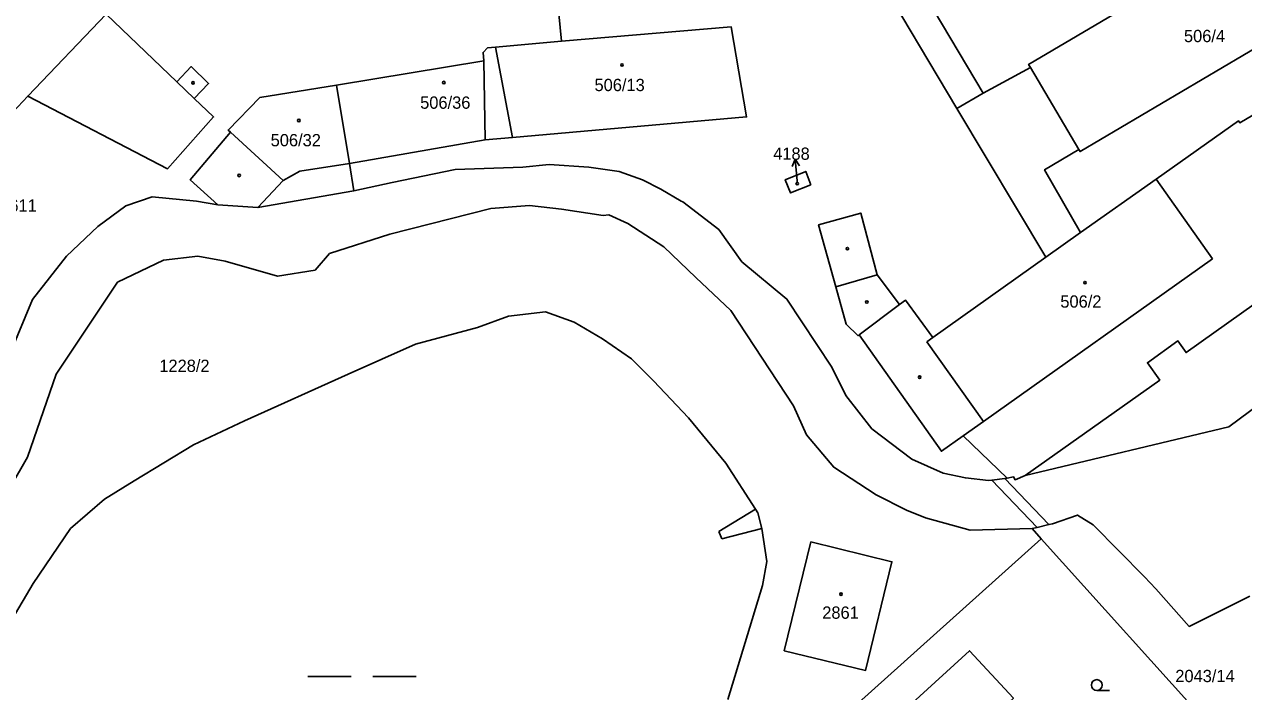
# Model space of a CAD drawing. Extents: x -679220 to -673243, y -1075091 to -1066557.
# Drawn here: x -677024.2 to -676855.4, y -1070809.1 to -1070716.7 of the extents above; entities that cross this region are included whole.
import ezdxf

# ---------------------------------------------------------------- set-up
doc = ezdxf.new("R2010")
doc.units = 0
for name, color, linetype in [('Hranice parcel', 7, 'Continuous'), ('Parcelní čísla', 7, 'Continuous'), ('Pop  PČ popisy', 7, 'Continuous'), ('Vnitřní kresba', 7, 'Continuous'), ('Značky budov', 7, 'Continuous'), ('Značky kultur', 7, 'Continuous')]:
    doc.layers.add(name, color=color, linetype=linetype)

msp = doc.modelspace()

# ---------------------------------------------------------------- linework, layer by layer
at = {"layer": 'Hranice parcel'}
for p, q in [((-676949.82, -1070719.08), (-676951.28, -1070703.69)), ((-676949.82, -1070719.08), (-676958.96, -1070719.87)), ((-676958.96, -1070719.87), (-676956.62, -1070732.39)), ((-676980.96, -1070725.14), (-676979.17, -1070736)), ((-676882.78, -1070748.97), (-676895.12, -1070728.36)), ((-676979.17, -1070736), (-676978.55, -1070739.75)), ((-676877.98, -1070745.56), (-676882.78, -1070748.97)), ((-676883.43, -1070787.92), (-676884.68, -1070786.53))]:
    msp.add_line(p, q, dxfattribs=at)
for points in [[(-676895.12, -1070728.36), (-676918.1, -1070689.75), (-676914.43, -1070687.67)], [(-677034.28, -1070697.59), (-677046.67, -1070710.74), (-677026.45, -1070729.62), (-677023.7, -1070726.67), (-677004.38, -1070736.72), (-676997.98, -1070729.55), (-677000.66, -1070726.99), (-676998.67, -1070724.91), (-677001.07, -1070722.57), (-677003.08, -1070724.67), (-677012.86, -1070715.31), (-677017.01, -1070711.34), (-677014.07, -1070708.12), (-677018.61, -1070704), (-677021.65, -1070707.35), (-677022.05, -1070707.36), (-677024.63, -1070704.99), (-677021.89, -1070702.22), (-677023.46, -1070700.67), (-677023.03, -1070700.24), (-677023.35, -1070699.92), (-677020.51, -1070697.05)], [(-676851.52, -1070702.41), (-676885.18, -1070722.27), (-676884.94, -1070722.68), (-676878.23, -1070734.06)], [(-676844.26, -1070714.41), (-676878.06, -1070734.35), (-676878.23, -1070734.06)], [(-676956.62, -1070732.39), (-676924.22, -1070729.55), (-676926.37, -1070717.06), (-676949.82, -1070719.08)], [(-676980.96, -1070725.14), (-676960.57, -1070721.79), (-676960.68, -1070720.61), (-676960.09, -1070720), (-676958.96, -1070719.87)], [(-676791.81, -1070723.66), (-676812.53, -1070740.21), (-676828.51, -1070750.96), (-676857.49, -1070772.45), (-676885.64, -1070779.16)], [(-676997.4, -1070741.72), (-677001.2, -1070738.24), (-676995.64, -1070731.65), (-676995.97, -1070731.36), (-676991.6, -1070726.87), (-676980.96, -1070725.14)], [(-676877.98, -1070745.56), (-676867.53, -1070738.15), (-676856.14, -1070730.08), (-676855.94, -1070730.37), (-676847.66, -1070725.47), (-676837.67, -1070742.46), (-676839.83, -1070743.73), (-676838.77, -1070745.52), (-676840.2, -1070746.36), (-676841.25, -1070744.57), (-676842.99, -1070745.59), (-676846.69, -1070748.21), (-676845.57, -1070749.9), (-676846.66, -1070750.67), (-676847.85, -1070749.03), (-676852.87, -1070752.58), (-676851.87, -1070754), (-676863.38, -1070762.15), (-676864.51, -1070760.55), (-676868.75, -1070763.56), (-676867.04, -1070765.97), (-676885.64, -1070779.16)], [(-676979.17, -1070736), (-676960.41, -1070732.72), (-676956.62, -1070732.39)], [(-676878.23, -1070734.06), (-676882.97, -1070736.85), (-676877.98, -1070745.56)], [(-676888.14, -1070779.54), (-676888.45, -1070779.58), (-676890.29, -1070779.8), (-676890.75, -1070779.86), (-676893.93, -1070779.51), (-676896.99, -1070778.86), (-676901.36, -1070776.91), (-676906.86, -1070772.7), (-676910.48, -1070768.1), (-676912.42, -1070764.19), (-676918.64, -1070754.75), (-676924.86, -1070749.59), (-676928.04, -1070745.14), (-676933.03, -1070741.3), (-676933.25, -1070741.19), (-676936.07, -1070739.53), (-676938.62, -1070738.27), (-676941.84, -1070737.1), (-676946.03, -1070736.49), (-676951.52, -1070736.14), (-676955.16, -1070736.5), (-676964.53, -1070736.83), (-676973.26, -1070738.63), (-676978.55, -1070739.75)], [(-676915.33, -1070738.94), (-676918.15, -1070740.06), (-676918.86, -1070738.23), (-676916.03, -1070737.09), (-676915.33, -1070738.94)], [(-676997.4, -1070741.72), (-677000.36, -1070741.19), (-677006.47, -1070740.6), (-677010.11, -1070741.84), (-677014, -1070744.73), (-677018.32, -1070748.82), (-677023.06, -1070754.8), (-677028.38, -1070767.57), (-677031.98, -1070774.25), (-677033.96, -1070775.82), (-677039.43, -1070784.79), (-677039.06, -1070786.18), (-677039.39, -1070786.77)], [(-676978.55, -1070739.75), (-676991.84, -1070742.1), (-676997.4, -1070741.72)], [(-677028.32, -1070784.52), (-677023.72, -1070776.62), (-677019.76, -1070765.14), (-677011.26, -1070752.43), (-677004.93, -1070749.36), (-677000.17, -1070748.82), (-676996.38, -1070749.52), (-676989.14, -1070751.58), (-676983.94, -1070750.74), (-676981.93, -1070748.44), (-676973.61, -1070745.79), (-676959.61, -1070742.23), (-676954.26, -1070741.78), (-676949.81, -1070742.3), (-676944.07, -1070743.19), (-676943.28, -1070743.1), (-676940.64, -1070744.29), (-676935.66, -1070747.52), (-676931.26, -1070751.78), (-676926.4, -1070756.34), (-676917.72, -1070769.51), (-676915.92, -1070773.56), (-676912.15, -1070778.02), (-676906.3, -1070781.87), (-676902.07, -1070783.96), (-676899.43, -1070785.04), (-676893.25, -1070786.74), (-676884.68, -1070786.53)], [(-676888.14, -1070779.54), (-676894.24, -1070773.67), (-676897.26, -1070775.81), (-676908.63, -1070759.7), (-676908.79, -1070759.82), (-676910.45, -1070758.24), (-676911.88, -1070753.04), (-676914.24, -1070744.49), (-676908.42, -1070742.85), (-676906.14, -1070751.39), (-676903.03, -1070755.49), (-676902.23, -1070754.89), (-676898.45, -1070760.08), (-676882.78, -1070748.97)], [(-676926.82, -1070810.18), (-676922.01, -1070794.4), (-676921.41, -1070791.08), (-676922.11, -1070786.53), (-676922.65, -1070784.32), (-676922.97, -1070783.82), (-676927.08, -1070777.48), (-676932.24, -1070771.18), (-676937.09, -1070766.07), (-676940.12, -1070763.03), (-676944.15, -1070760.28), (-676948.06, -1070757.96), (-676952.05, -1070756.53), (-676957.18, -1070757.14), (-676961.46, -1070758.7), (-676970.02, -1070761.01), (-676979.34, -1070765.15), (-676993.71, -1070771.59), (-677000.78, -1070774.92), (-677008.99, -1070779.92), (-677013.06, -1070782.43), (-677017.8, -1070786.51), (-677022.97, -1070794.1), (-677028.35, -1070803.23)], [(-676885.64, -1070779.16), (-676887.05, -1070779.75), (-676887.25, -1070779.37), (-676888.14, -1070779.54)], [(-676884.68, -1070786.53), (-676884, -1070786.36), (-676882.36, -1070785.96), (-676881.88, -1070785.84), (-676878.42, -1070784.64), (-676876.26, -1070786.01), (-676869.13, -1070793.18), (-676867.57, -1070794.88), (-676862.94, -1070800.05), (-676854.56, -1070795.88)], [(-676919.02, -1070803.46), (-676907.75, -1070806.14), (-676904.1, -1070791.12), (-676915.32, -1070788.37), (-676919.02, -1070803.46)], [(-676883.43, -1070787.92), (-676917.3, -1070818.34), (-676914.74, -1070823.1)], [(-676855.98, -1070818.07), (-676856.99, -1070816.97), (-676859.43, -1070814.62), (-676883.43, -1070787.92)], [(-676914.74, -1070823.1), (-676913.55, -1070822.17), (-676909.63, -1070818.26), (-676910.25, -1070817.54), (-676908.84, -1070816.2), (-676908.18, -1070816.94), (-676893.35, -1070803.44), (-676887.28, -1070809.99), (-676898.98, -1070820.81)]]:
    msp.add_lwpolyline(points, dxfattribs=at)
at = {"layer": 'Pop  PČ popisy'}
for p, q in [((-676917.49, -1070735.38), (-676917.9, -1070736.42)), ((-676917.23, -1070738.37), (-676917.49, -1070735.38)), ((-676917.49, -1070735.38), (-676916.91, -1070736.33)), ((-676917.21, -1070738.61), (-676917.23, -1070738.37))]:
    msp.add_line(p, q, dxfattribs=at)
at = {"layer": 'Vnitřní kresba'}
for p, q in [((-676914.43, -1070687.67), (-676891.45, -1070726.25)), ((-677023.7, -1070726.67), (-677012.86, -1070715.31)), ((-676960.57, -1070721.79), (-676960.41, -1070732.72)), ((-676891.45, -1070726.25), (-676884.94, -1070722.68)), ((-677003.08, -1070724.67), (-677000.66, -1070726.99)), ((-676891.45, -1070726.25), (-676895.12, -1070728.36)), ((-676995.64, -1070731.65), (-676988.37, -1070738.34)), ((-676986.03, -1070737.05), (-676979.17, -1070736)), ((-676988.37, -1070738.34), (-676986.03, -1070737.05)), ((-676991.84, -1070742.1), (-676988.37, -1070738.34)), ((-676867.53, -1070738.15), (-676859.71, -1070749.17)), ((-676859.71, -1070749.17), (-676891.44, -1070771.68)), ((-676911.88, -1070753.04), (-676906.14, -1070751.39)), ((-676908.63, -1070759.7), (-676903.03, -1070755.49)), ((-676899.26, -1070760.66), (-676898.45, -1070760.08)), ((-676891.44, -1070771.68), (-676899.26, -1070760.66)), ((-676891.44, -1070771.68), (-676894.24, -1070773.67)), ((-676890.29, -1070779.8), (-676884, -1070786.36)), ((-676888.45, -1070779.58), (-676882.36, -1070785.96)), ((-676928.07, -1070786.93), (-676922.97, -1070783.82)), ((-676922.11, -1070786.53), (-676927.63, -1070787.96)), ((-676927.63, -1070787.96), (-676928.07, -1070786.93))]:
    msp.add_line(p, q, dxfattribs=at)
at = {"layer": 'Značky budov'}
for centre in [(-676941.46, -1070722.35), (-677000.82, -1070724.83), (-676966.11, -1070724.79), (-676986.19, -1070730.04), (-676994.44, -1070737.64), (-676917.2, -1070738.78), (-676910.26, -1070747.77), (-676877.38, -1070752.49), (-676907.57, -1070755.16), (-676900.26, -1070765.57), (-676911.15, -1070795.59)]:
    msp.add_circle(centre, 0.175, dxfattribs=at)
at = {"layer": 'Značky kultur'}
for p, q in [((-676984.92, -1070806.97), (-676978.92, -1070806.97)), ((-676975.92, -1070806.97), (-676969.92, -1070806.97)), ((-676875.74, -1070808.92), (-676873.99, -1070808.92))]:
    msp.add_line(p, q, dxfattribs=at)
msp.add_circle((-676875.74, -1070808.17), 0.75, dxfattribs=at)

# ---------------------------------------------------------------- texts
at = {"layer": 'Parcelní čísla'}
for s, p in [('506/4', (-676863.68, -1070719.19)), ('506/13', (-676945.26, -1070725.97)), ('506/36', (-676969.39, -1070728.41)), ('506/32', (-676990.08, -1070733.61)), ('4188', (-676920.53, -1070735.48)), ('2611', (-677027.51, -1070742.65)), ('506/2', (-676880.79, -1070755.94)), ('1228/2', (-677005.49, -1070764.84)), ('2861', (-676913.74, -1070799)), ('2043/14', (-676864.88, -1070807.77))]:
    msp.add_text(s, height=1.7, dxfattribs=at).set_placement(p)

doc.saveas('drawing.dxf')
